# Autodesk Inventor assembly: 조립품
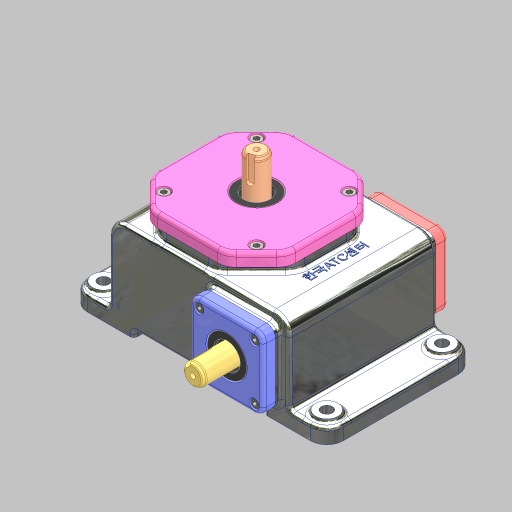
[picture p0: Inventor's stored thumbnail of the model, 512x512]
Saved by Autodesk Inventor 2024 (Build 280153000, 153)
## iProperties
Created: 2026-02
Part Number: 조립품
Document SubType Name: Assembly
Designer: 2-10
Author: 2-10
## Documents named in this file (14)
- C:\Users\2-10\Desktop\760203V1009\조립품.iam
- C:\Users\2-10\Desktop\760203V1009\조립품.ipt
- C:\Users\2-10\Desktop\760203V1009\웜 휠 커버\웜 휠 커버.ipt
- C:\Users\2-10\Desktop\760203V1009\6각 구멍붙이 볼트 M5x10\6각 구멍붙이 볼트 M5x10.ipt
- C:\Users\2-10\Desktop\760203V1009\뒷커버\뒷커버.ipt
- C:\Users\2-10\Desktop\760203V1009\앞커버\앞커버.ipt
- C:\Users\2-10\Desktop\760203V1009\오일 실 17 32 8\오일 실 17 32 8.ipt
- C:\Users\2-10\Desktop\760203V1009\웜 샤프트\웜 샤프트.ipt
- C:\Users\2-10\Desktop\760203V1009\웜 휠\웜 휠.ipt
- C:\Users\2-10\Desktop\760203V1009\축\축.ipt
- C:\Users\2-10\Desktop\760203V1009\칼라\칼라.ipt
- C:\Users\2-10\Desktop\760203V1009\테이퍼 롤러 베어링 30203\테이퍼 롤러 베어링 30203.ipt
- C:\Users\2-10\Desktop\760203V1009\평행 키 5x5x16\평행 키 5x5x16.ipt
- C:\Users\2-10\Desktop\760203V1009\6각 구멍붙이 볼트 M4x10\6각 구멍붙이 볼트 M4x10.ipt
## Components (12 placed, 2 different names)
1. 6각 구멍붙이 볼트 M5x10:9
2. 6각 구멍붙이 볼트 M5x10:10
3. 6각 구멍붙이 볼트 M5x10:11
4. 6각 구멍붙이 볼트 M5x10:12
5. 6각 구멍붙이 볼트 M4x10:1
6. 6각 구멍붙이 볼트 M4x10:2
7. 6각 구멍붙이 볼트 M4x10:3
8. 6각 구멍붙이 볼트 M4x10:4
9. 6각 구멍붙이 볼트 M4x10:5
10. 6각 구멍붙이 볼트 M4x10:6
11. 6각 구멍붙이 볼트 M4x10:7
12. 6각 구멍붙이 볼트 M4x10:8
